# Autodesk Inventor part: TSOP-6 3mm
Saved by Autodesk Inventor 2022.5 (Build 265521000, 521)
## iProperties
Created: 2024-12
Part Number: TSOP-6 3mm
Material: Generic
Document SubType Name: Modeling
Designer: AdminForWorker
Density: 1 g/cm^3
Appearance: Default
Title: TSOP-6 3mm v1
Author: AdminForWorker
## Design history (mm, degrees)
feature "Body1" [lead]
feature "lead2"
feature "lead1"
feature "lead3"
feature "opt_lead" [lead]
feature "lead5"
feature "lead4"
body "Solid1"
body "Solid2"
body "Solid3"
body "Solid4"
body "Solid5"
body "Solid6"
body "Solid7"
